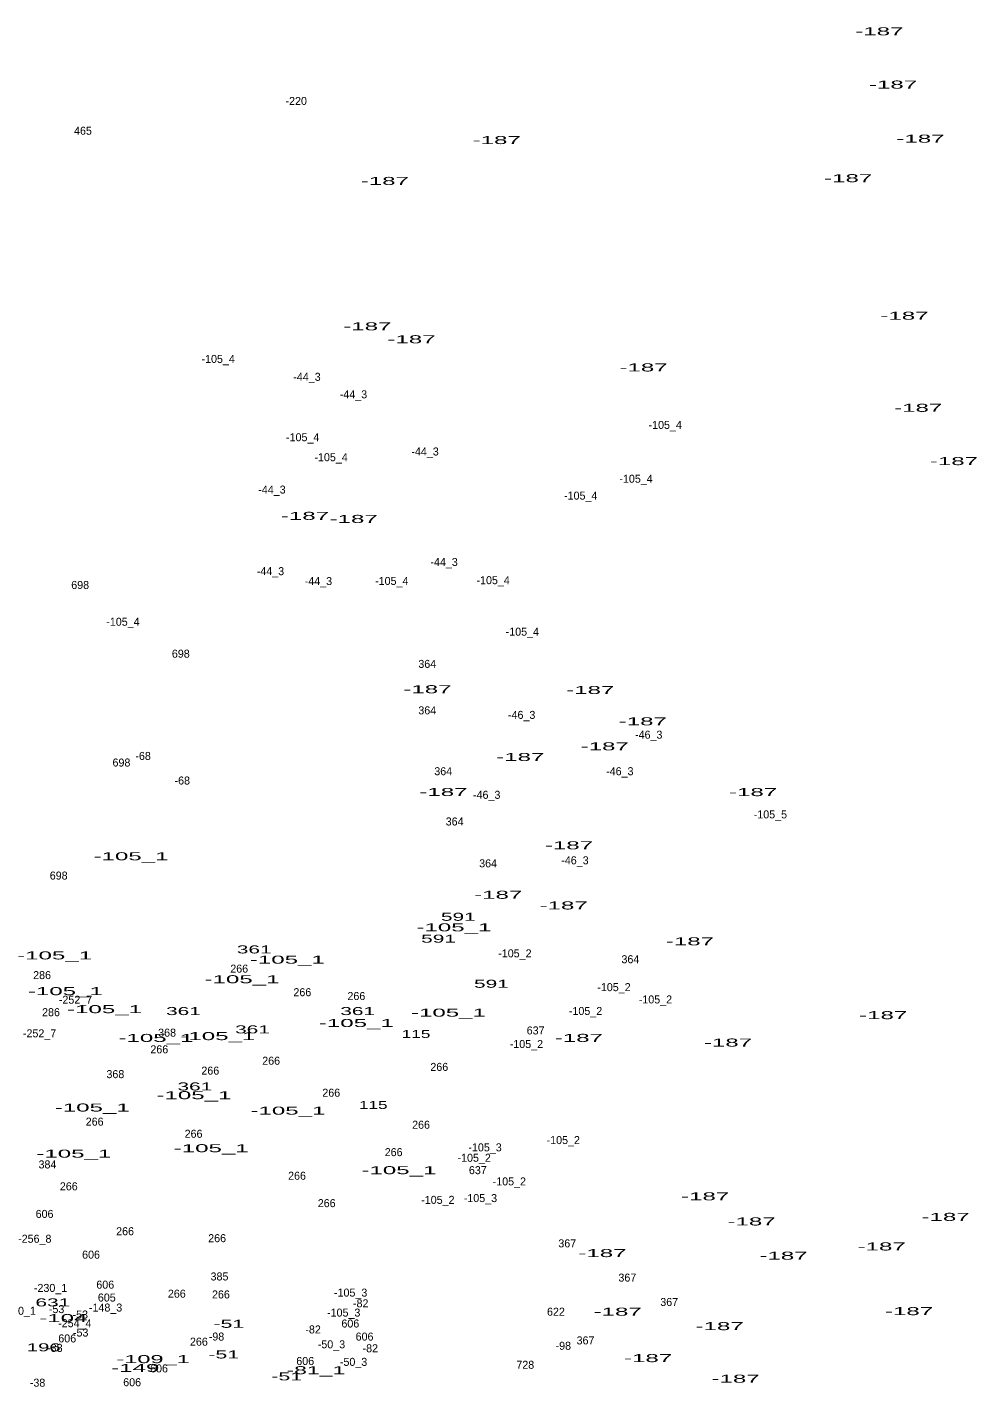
# Model space of a CAD drawing. Extents: x -658595 to -655205, y -1004347 to -1000147.
# Drawn here: x -655888 to -655414, y -1002919 to -1002239 of the extents above; entities that cross this region are included whole.
import ezdxf
from ezdxf.enums import TextEntityAlignment as Align

# ---------------------------------------------------------------- set-up
doc = ezdxf.new("R2010")
doc.units = 0
doc.header["$LTSCALE"] = 1.6
doc.layers.add('24', color=7, linetype='Continuous')

msp = doc.modelspace()

# ---------------------------------------------------------------- texts
at = {"layer": '24'}
for s, width, p in [('-187', 2.25, (-655462.325, -1002243.26)), ('-187', 2.25, (-655455.485, -1002269.89)), ('-187', 2.25, (-655653.645, -1002297.62)), ('-187', 2.25, (-655441.785, -1002296.91)), ('-187', 2.25, (-655709.565, -1002318.05)), ('-187', 2.25, (-655477.925, -1002316.67)), ('-187', 2.25, (-655449.775, -1002385.42)), ('-187', 2.25, (-655718.315, -1002390.72)), ('-187', 2.25, (-655696.245, -1002397.19)), ('-187', 2.25, (-655580.235, -1002411.27)), ('-187', 2.25, (-655442.925, -1002431.46)), ('-187', 2.25, (-655425.055, -1002458.09)), ('-187', 2.25, (-655749.505, -1002485.47)), ('-187', 2.25, (-655725.155, -1002486.99)), ('-187', 2.25, (-655688.265, -1002572.12)), ('-187', 2.25, (-655606.865, -1002572.5)), ('-187', 2.25, (-655580.615, -1002588.16)), ('-187', 2.25, (-655641.855, -1002605.99)), ('-187', 2.25, (-655599.635, -1002600.66)), ('-187', 2.25, (-655680.275, -1002623.49)), ('-187', 2.25, (-655525.465, -1002623.55)), ('-187', 2.25, (-655617.515, -1002650.13)), ('-105_1', 2.25, (-655836.464, -1002655.62)), ('-187', 2.25, (-655652.885, -1002674.86)), ('-187', 2.25, (-655620.175, -1002680.19)), ('591', 1.95, (-655672.843, -1002685.86)), ('-105_1', 2.25, (-655675.044, -1002691.14)), ('591', 1.95, (-655682.723, -1002696.79)), ('-187', 2.25, (-655557.035, -1002698.13)), ('-105_1', 2.25, (-655874.674, -1002705.17)), ('361', 1.95, (-655774.883, -1002702.17)), ('-105_1', 2.25, (-655758.314, -1002707.29)), ('-105_1', 2.25, (-655780.974, -1002717.08)), ('591', 1.95, (-655656.293, -1002719.34)), ('-105_1', 2.25, (-655869.294, -1002723.04)), ('-105_1', 2.25, (-655849.714, -1002732.04)), ('361', 1.95, (-655810.263, -1002732.99)), ('361', 1.95, (-655723.153, -1002732.99)), ('-105_1', 2.25, (-655677.764, -1002733.78)), ('-187', 2.25, (-655460.425, -1002735.04)), ('361', 1.95, (-655775.743, -1002742.15)), ('-105_1', 2.25, (-655723.814, -1002738.96)), ('-105_1', 2.25, (-655824.014, -1002746.42)), ('-105_1', 2.25, (-655793.064, -1002745.51)), ('115', 1.6, (-655693.954, -1002744.45)), ('-187', 2.25, (-655612.565, -1002746.39)), ('-187', 2.25, (-655538.015, -1002748.73)), ('-105_1', 2.25, (-655805.014, -1002775.04)), ('361', 1.95, (-655804.553, -1002770.66)), ('-105_1', 2.25, (-655855.854, -1002781.21)), ('-105_1', 2.25, (-655758.024, -1002782.76)), ('115', 1.6, (-655715.354, -1002779.93)), ('-105_1', 2.25, (-655796.374, -1002801.55)), ('-105_1', 2.25, (-655865.074, -1002804.26)), ('-105_1', 2.25, (-655702.534, -1002812.53)), ('-187', 2.25, (-655549.425, -1002825.59)), ('-187', 2.25, (-655429.235, -1002835.87)), ('-187', 2.25, (-655526.225, -1002838.15)), ('-187', 2.25, (-655461.185, -1002850.65)), ('-187', 2.25, (-655600.775, -1002853.96)), ('-187', 2.25, (-655510.245, -1002855.27)), ('631', 1.95, (-655875.563, -1002878.61)), ('-187', 2.25, (-655593.165, -1002883.26)), ('-187', 2.25, (-655447.485, -1002882.99)), ('-104', 2.25, (-655870.312, -1002886.45)), ('-51', 2, (-655787.561, -1002889.3)), ('-187', 2.25, (-655542.195, -1002890.49)), ('196', 1.9, (-655880.117, -1002901.06)), ('-51', 2, (-655790.131, -1002904.63)), ('-149', 2.25, (-655834.351, -1002911.38)), ('-109_1', 2.2, (-655825.439, -1002906.96)), ('-81_1', 2.15, (-655744.037, -1002912.5)), ('-187', 2.25, (-655577.955, -1002906.47)), ('-51', 2, (-655758.621, -1002915.59)), ('-187', 2.25, (-655534.215, -1002916.75))]:
    msp.add_text(s, height=4, dxfattribs=dict(at, width=width)).set_placement(p, align=Align.CENTER)
for s, p in [('-220', (-655753.879, -1002278.07)), ('465', (-655860.487, -1002292.95)), ('-105_4', (-655792.894, -1002407.01)), ('-44_3', (-655748.501, -1002415.96)), ('-44_3', (-655725.261, -1002424.71)), ('-105_4', (-655569.404, -1002440.01)), ('-105_4', (-655750.654, -1002446.16)), ('-105_4', (-655736.444, -1002456.14)), ('-44_3', (-655689.471, -1002453.29)), ('-105_4', (-655583.994, -1002466.9)), ('-44_3', (-655766.011, -1002472.33)), ('-105_4', (-655611.644, -1002475.35)), ('-44_3', (-655679.951, -1002508.52)), ('-44_3', (-655766.771, -1002513.1)), ('-44_3', (-655742.781, -1002518.05)), ('-105_4', (-655706.114, -1002517.99)), ('-105_4', (-655655.424, -1002517.61)), ('698', (-655861.898, -1002520)), ('-105_4', (-655840.514, -1002538.39)), ('-105_4', (-655640.834, -1002543.35)), ('698', (-655811.588, -1002554.35)), ('364', (-655688.377, -1002559.46)), ('364', (-655688.377, -1002582.67)), ('-46_3', (-655641.162, -1002584.95)), ('-46_3', (-655577.642, -1002594.84)), ('-68', (-655830.43, -1002605.46)), ('698', (-655841.258, -1002608.76)), ('364', (-655680.387, -1002613.11)), ('-46_3', (-655592.092, -1002613.11)), ('-68', (-655810.85, -1002617.76)), ('-46_3', (-655658.652, -1002624.9)), ('364', (-655674.687, -1002638.22)), ('-105_5', (-655516.82, -1002634.68)), ('364', (-655657.947, -1002659.15)), ('-46_3', (-655614.532, -1002657.63)), ('698', (-655872.638, -1002665.26)), ('-105_2', (-655644.56, -1002704.14)), ('364', (-655586.817, -1002707.09)), ('286', (-655880.953, -1002715.02)), ('266', (-655782.388, -1002711.78)), ('-105_2', (-655595.02, -1002721.04)), ('-252_7', (-655864.228, -1002727.31)), ('266', (-655750.818, -1002723.57)), ('266', (-655723.808, -1002725.48)), ('-105_2', (-655574.29, -1002727.18)), ('286', (-655876.483, -1002733.56)), ('-105_2', (-655609.23, -1002732.95)), ('637', (-655634.188, -1002742.68)), ('-252_7', (-655882.188, -1002744.12)), ('368', (-655818.433, -1002743.78)), ('-105_2', (-655638.8, -1002749.47)), ('266', (-655822.328, -1002752.11)), ('266', (-655796.838, -1002762.76)), ('266', (-655766.418, -1002757.82)), ('266', (-655682.358, -1002760.9)), ('368', (-655844.303, -1002764.52)), ('266', (-655736.368, -1002773.8)), ('266', (-655854.658, -1002788.26)), ('266', (-655691.478, -1002789.82)), ('266', (-655805.208, -1002794.32)), ('266', (-655705.178, -1002803.52)), ('-105_3', (-655659.47, -1002801.12)), ('-105_2', (-655620.37, -1002797.48)), ('384', (-655878.251, -1002809.65)), ('-105_2', (-655664.91, -1002806.32)), ('266', (-655753.478, -1002815.31)), ('637', (-655663.088, -1002812.51)), ('266', (-655867.588, -1002820.6)), ('-105_2', (-655647.34, -1002818.13)), ('266', (-655738.648, -1002829.01)), ('-105_2', (-655683.06, -1002827.35)), ('-105_3', (-655661.78, -1002826.47)), ('606', (-655879.692, -1002834.39)), ('266', (-655839.448, -1002843.05)), ('-256_8', (-655884.588, -1002846.8)), ('266', (-655793.418, -1002846.51)), ('367', (-655618.378, -1002849.1)), ('606', (-655856.462, -1002854.75)), ('-230_1', (-655876.69, -1002871.38)), ('606', (-655849.352, -1002869.74)), ('385', (-655792.247, -1002865.65)), ('367', (-655588.328, -1002866.22)), ('605', (-655848.587, -1002876.19)), ('266', (-655813.578, -1002874.25)), ('266', (-655791.518, -1002874.64)), ('-105_3', (-655726.67, -1002873.72)), ('367', (-655567.408, -1002878.4)), ('-230_1', (-655892.37, -1002882.8)), ('-53', (-655873.685, -1002881.96)), ('-53', (-655861.835, -1002884.68)), ('-148_3', (-655849.19, -1002881.19)), ('-105_3', (-655730.13, -1002883.71)), ('-82', (-655721.635, -1002879.07)), ('622', (-655624.033, -1002883.27)), ('-254_4', (-655864.571, -1002889.02)), ('-82', (-655745.445, -1002892.13)), ('606', (-655726.822, -1002889.17)), ('606', (-655868.362, -1002896.62)), ('-53', (-655861.645, -1002893.68)), ('266', (-655802.548, -1002898.24)), ('-98', (-655793.74, -1002895.69)), ('606', (-655719.712, -1002895.7)), ('367', (-655609.248, -1002897.61)), ('-38', (-655874.545, -1002901.34)), ('-50_3', (-655736.256, -1002899.57)), ('-82', (-655716.835, -1002901.54)), ('-98', (-655620.36, -1002900.3)), ('606', (-655822.472, -1002911.61)), ('606', (-655749.382, -1002907.9)), ('-50_3', (-655725.206, -1002908.33)), ('728', (-655639.363, -1002909.79)), ('-38', (-655883.195, -1002918.75)), ('606', (-655835.912, -1002918.52))]:
    msp.add_text(s, height=4, dxfattribs=at).set_placement(p, align=Align.CENTER)

doc.saveas('drawing.dxf')
